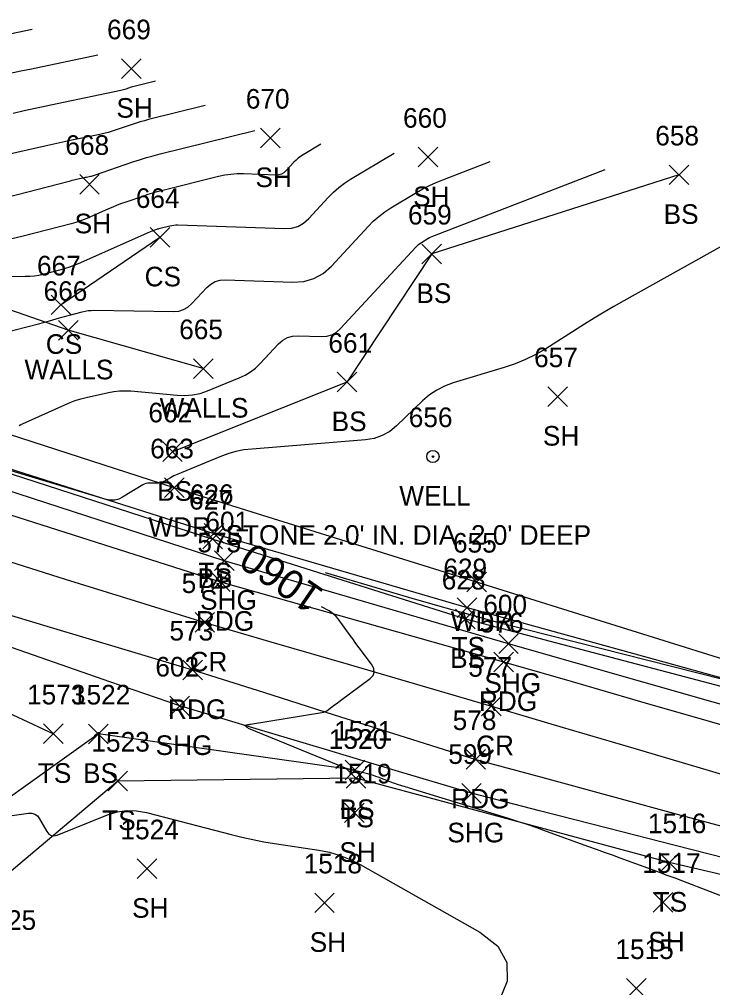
# Model space of a CAD drawing. Extents: x 1592612 to 1596497, y 111838 to 113741.
# Drawn here: x 1593003.9 to 1593074.6, y 113362.1 to 113460.8 of the extents above; entities that cross this region are included whole.
import ezdxf

# ---------------------------------------------------------------- set-up
doc = ezdxf.new("R2010")
doc.units = 0
for name, color, linetype in [('L_A', 7, 'Continuous'), ('L_I', 7, 'Continuous'), ('L_TIC', 7, 'Continuous'), ('LAWA', 7, 'Continuous'), ('LELB', 7, 'Continuous'), ('LSOGCMA', 7, 'Continuous'), ('LSOGCMA_T', 7, 'Continuous'), ('LSOGCMI', 7, 'Continuous'), ('LWS', 7, 'Continuous'), ('P_A', 7, 'Continuous'), ('P_I', 7, 'Continuous'), ('P_TIC', 7, 'Continuous'), ('PEU', 7, 'Continuous'), ('PRC', 7, 'Continuous'), ('PSU', 7, 'Continuous'), ('U_A', 7, 'Continuous'), ('U_C', 7, 'Continuous'), ('U_I', 7, 'Continuous'), ('UWW', 7, 'Continuous')]:
    doc.layers.add(name, color=color, linetype=linetype)

msp = doc.modelspace()

# ---------------------------------------------------------------- linework, layer by layer
at = {"layer": 'L_TIC'}
for points in [[(1593014.335, 113454.79), (1593016.335, 113456.79)], [(1593016.335, 113454.79), (1593014.335, 113456.79)], [(1593028.518, 113447.717), (1593030.518, 113449.717)], [(1593030.518, 113447.717), (1593028.518, 113449.717)], [(1593044.604, 113445.772), (1593046.604, 113447.772)], [(1593046.604, 113445.772), (1593044.604, 113447.772)], [(1593070.196, 113443.965), (1593072.196, 113445.965)], [(1593072.196, 113443.965), (1593070.196, 113445.965)], [(1593010.076, 113443.003), (1593012.076, 113445.003)], [(1593012.076, 113443.003), (1593010.076, 113445.003)], [(1593017.258, 113437.593), (1593019.258, 113439.593)], [(1593019.258, 113437.593), (1593017.258, 113439.593)], [(1593044.981, 113435.899), (1593046.981, 113437.899)], [(1593046.981, 113435.899), (1593044.981, 113437.899)], [(1593007.179, 113430.713), (1593009.179, 113432.713)], [(1593009.179, 113430.713), (1593007.179, 113432.713)], [(1593007.908, 113428.114), (1593009.908, 113430.114)], [(1593009.908, 113428.114), (1593007.908, 113430.114)], [(1593021.683, 113424.211), (1593023.683, 113426.211)], [(1593023.683, 113424.211), (1593021.683, 113426.211)], [(1593036.335, 113422.831), (1593038.335, 113424.831)], [(1593038.335, 113422.831), (1593036.335, 113424.831)], [(1593057.836, 113421.356), (1593059.836, 113423.356)], [(1593059.836, 113421.356), (1593057.836, 113423.356)], [(1593018.544, 113415.731), (1593020.544, 113417.731)], [(1593020.544, 113415.731), (1593018.544, 113417.731)], [(1593018.72, 113412.06), (1593020.72, 113414.06)], [(1593020.72, 113412.06), (1593018.72, 113414.06)], [(1593022.772, 113407.407), (1593024.772, 113409.407)], [(1593024.772, 113407.407), (1593022.772, 113409.407)], [(1593022.641, 113406.833), (1593024.641, 113408.833)], [(1593024.641, 113406.833), (1593022.641, 113408.833)], [(1593049.562, 113402.447), (1593051.562, 113404.447)], [(1593051.562, 113402.447), (1593049.562, 113404.447)], [(1593048.589, 113399.837), (1593050.589, 113401.837)], [(1593050.589, 113399.837), (1593048.589, 113401.837)], [(1593048.418, 113398.686), (1593050.418, 113400.686)], [(1593050.418, 113398.686), (1593048.418, 113400.686)], [(1593006.402, 113386.97), (1593008.402, 113388.97)], [(1593008.402, 113386.97), (1593006.402, 113388.97)], [(1593010.98, 113386.959), (1593012.98, 113388.959)], [(1593012.98, 113386.959), (1593010.98, 113388.959)], [(1593037.15, 113383.278), (1593039.15, 113385.278)], [(1593039.15, 113383.278), (1593037.15, 113385.278)], [(1593037.268, 113382.436), (1593039.268, 113384.436)], [(1593039.268, 113382.436), (1593037.268, 113384.436)], [(1593012.967, 113382.154), (1593014.967, 113384.154)], [(1593014.967, 113382.154), (1593012.967, 113384.154)], [(1593037.078, 113378.911), (1593039.078, 113380.911)], [(1593039.078, 113378.911), (1593037.078, 113380.911)], [(1593069.216, 113373.835), (1593071.216, 113375.835)], [(1593071.216, 113373.835), (1593069.216, 113375.835)], [(1593015.932, 113373.213), (1593017.932, 113375.213)], [(1593017.932, 113373.213), (1593015.932, 113375.213)], [(1593034.047, 113369.735), (1593036.047, 113371.735)], [(1593036.047, 113369.735), (1593034.047, 113371.735)], [(1593068.583, 113369.781), (1593070.583, 113371.781)], [(1593070.583, 113369.781), (1593068.583, 113371.781)], [(1593065.844, 113361.005), (1593067.844, 113363.005)], [(1593067.844, 113361.005), (1593065.844, 113363.005)]]:
    msp.add_lwpolyline(points, dxfattribs=at)
at = {"layer": 'LAWA'}
msp.add_lwpolyline([(1593169.611, 113375.165), (1593118.398, 113387.407), (1593080.143, 113394.184), (1593050.562, 113403.447), (1593019.72, 113413.06), (1592995.657, 113420.841), (1592970.681, 113431.184), (1592941.873, 113445.585), (1592917.884, 113456.286)], dxfattribs=at)
at = {"layer": 'LELB'}
for points in [[(1592908.46, 113460.258), (1592922.596, 113449.566), (1592933.267, 113441.549), (1592945.1, 113436.529), (1592970.28, 113425.515), (1592997.076, 113416.402), (1593023.641, 113407.833), (1593049.418, 113399.686), (1593079.204, 113391.835), (1593097.266, 113387.672), (1593130.658, 113380.878), (1593168.554, 113372.43)], [(1593071.196, 113444.965), (1593045.981, 113436.9), (1593037.335, 113423.831), (1593019.544, 113416.731)], [(1593018.258, 113438.593), (1593008.179, 113431.713)], [(1592945.373, 113437.303), (1592970.416, 113426.096), (1592997.179, 113416.812), (1593023.772, 113408.406), (1593049.589, 113400.837), (1593079.367, 113392.638), (1593097.503, 113388.59), (1593131.295, 113382.361), (1593169.279, 113374.833)], [(1593022.223, 113298.621), (1592996.05, 113319.251), (1592973.737, 113329.884), (1592951.567, 113338.734), (1592939.58, 113363.449), (1592930.763, 113371.375), (1592929.879, 113381.446), (1592924.735, 113386.602), (1592927.418, 113411.322), (1592932.961, 113414.131), (1592945.073, 113412.416), (1592963.598, 113404.825), (1592977.398, 113399.854), (1592996.446, 113393.062), (1593007.402, 113387.97)], [(1593038.151, 113384.278), (1593011.98, 113387.959), (1592995.33, 113376.06), (1592980.31, 113354.964), (1592972.203, 113338.996)], [(1593157.216, 113351.758), (1593128.266, 113360.771), (1593100.017, 113367.909), (1593070.216, 113374.835), (1593038.268, 113383.437), (1593013.967, 113383.154), (1593000.038, 113371.416), (1592985.819, 113350.727), (1592975.861, 113332.672)]]:
    msp.add_lwpolyline(points, dxfattribs=at)
at = {"layer": 'LSOGCMA'}
for points in [[(1593001.623, 113459.084), (1593005.243, 113459.837)], [(1593034.685, 113448.092), (1593032.859, 113446.998), (1593032.608, 113446.835), (1593032.37, 113446.656), (1593032.145, 113446.46), (1593031.935, 113446.247), (1593031.118, 113445.364), (1593030.902, 113445.172), (1593030.662, 113445.038), (1593030.397, 113444.961), (1593030.109, 113444.943), (1593026.801, 113445.058), (1593026.152, 113445.058), (1593025.508, 113445.013), (1593024.868, 113444.924), (1593024.233, 113444.789), (1593018.411, 113443.345), (1593017.952, 113443.225), (1593017.495, 113443.096), (1593017.041, 113442.956), (1593016.591, 113442.807), (1593014.793, 113442.189), (1593014.346, 113442.029), (1593013.902, 113441.861), (1593013.462, 113441.682), (1593013.026, 113441.495), (1593011.115, 113440.648), (1593010.649, 113440.453), (1593010.175, 113440.277), (1593009.695, 113440.121), (1593009.208, 113439.985), (1593004.159, 113438.682), (1593003.15, 113438.455)], [(1593035.109, 113404.404), (1593043.616, 113401.897), (1593046.557, 113401.047), (1593049.505, 113400.225), (1593052.462, 113399.432), (1593055.426, 113398.668), (1593078.233, 113392.909)], [(1593077.227, 113370.76), (1593071.605, 113372.928), (1593070.809, 113373.233), (1593070.011, 113373.534), (1593069.212, 113373.832), (1593068.412, 113374.126), (1593065.208, 113375.295), (1593064.407, 113375.587), (1593063.605, 113375.879), (1593062.804, 113376.17), (1593062.002, 113376.461), (1593057.695, 113378.022), (1593056.708, 113378.373), (1593055.716, 113378.712), (1593054.721, 113379.039), (1593053.722, 113379.353), (1593043.706, 113382.432), (1593043.542, 113382.483), (1593043.378, 113382.533), (1593043.215, 113382.584), (1593043.051, 113382.635), (1593042.397, 113382.839), (1593042.234, 113382.891), (1593042.072, 113382.946), (1593041.911, 113383.004), (1593041.751, 113383.065), (1593040.515, 113383.544), (1593040.285, 113383.63), (1593040.053, 113383.709), (1593039.819, 113383.782), (1593039.582, 113383.848), (1593038.249, 113384.203), (1593038.203, 113384.214), (1593038.157, 113384.223), (1593038.11, 113384.231), (1593038.063, 113384.236), (1593037.873, 113384.253), (1593037.827, 113384.258), (1593037.782, 113384.266), (1593037.737, 113384.277), (1593037.693, 113384.291), (1593037.517, 113384.35), (1593037.474, 113384.365), (1593037.43, 113384.381), (1593037.387, 113384.397), (1593037.344, 113384.415), (1593027.307, 113388.521), (1593027.258, 113388.543), (1593027.211, 113388.569), (1593027.167, 113388.598), (1593027.124, 113388.631), (1593026.958, 113388.768), (1593026.929, 113388.799), (1593026.923, 113388.825), (1593026.94, 113388.844), (1593026.981, 113388.857), (1593027.241, 113388.908), (1593027.301, 113388.92), (1593027.362, 113388.931), (1593027.423, 113388.941), (1593027.485, 113388.952), (1593034.763, 113390.138), (1593034.95, 113390.18), (1593035.127, 113390.244), (1593035.295, 113390.329), (1593035.454, 113390.437), (1593036.07, 113390.909), (1593036.224, 113391.027), (1593036.379, 113391.144), (1593036.534, 113391.261), (1593036.689, 113391.377), (1593039.692, 113393.606), (1593039.995, 113393.905), (1593040.129, 113394.23), (1593040.096, 113394.58), (1593039.895, 113394.955), (1593038.72, 113396.555), (1593038.453, 113396.918), (1593038.187, 113397.281), (1593037.921, 113397.644), (1593037.654, 113398.007), (1593036.428, 113399.679), (1593036.232, 113399.919), (1593036.013, 113400.135), (1593035.773, 113400.327), (1593035.511, 113400.493), (1593034.742, 113400.926)]]:
    msp.add_lwpolyline(points, dxfattribs=at)
at = {"layer": 'LSOGCMI'}
for points in [[(1593011.914, 113457.162), (1593005.15, 113455.755), (1593004.075, 113455.529), (1593003.001, 113455.299)], [(1593003.276, 113451.262), (1593004.402, 113451.514), (1593005.528, 113451.761), (1593006.656, 113452.003), (1593007.785, 113452.241), (1593014.284, 113453.593), (1593014.423, 113453.624), (1593014.56, 113453.659), (1593014.696, 113453.699), (1593014.831, 113453.743), (1593015.368, 113453.928), (1593015.502, 113453.972), (1593015.638, 113454.014), (1593015.774, 113454.053), (1593015.912, 113454.088), (1593017.806, 113454.558)], [(1593022.877, 113452.029), (1593017.095, 113450.594), (1593016.676, 113450.485), (1593016.259, 113450.367), (1593015.845, 113450.24), (1593015.434, 113450.103), (1593013.795, 113449.539), (1593013.383, 113449.405), (1593012.968, 113449.284), (1593012.549, 113449.176), (1593012.126, 113449.081), (1593009.284, 113448.489), (1593008.669, 113448.36), (1593008.055, 113448.228), (1593007.441, 113448.094), (1593006.828, 113447.957), (1593001.517, 113446.758)], [(1593001.456, 113442.383), (1593008.997, 113444.328), (1593009.154, 113444.368), (1593009.312, 113444.407), (1593009.471, 113444.445), (1593009.629, 113444.481), (1593010.38, 113444.651), (1593010.48, 113444.673), (1593010.581, 113444.695), (1593010.682, 113444.717), (1593010.782, 113444.738), (1593011.186, 113444.822), (1593011.286, 113444.845), (1593011.386, 113444.87), (1593011.484, 113444.899), (1593011.582, 113444.931), (1593015.5, 113446.279), (1593016.188, 113446.507), (1593016.88, 113446.72), (1593017.577, 113446.918), (1593018.279, 113447.1), (1593027.949, 113449.499)], [(1592997.854, 113434.611), (1593004.526, 113434.619), (1593004.992, 113434.635), (1593005.454, 113434.679), (1593005.913, 113434.752), (1593006.367, 113434.854), (1593008.179, 113435.322), (1593008.629, 113435.448), (1593009.072, 113435.592), (1593009.51, 113435.754), (1593009.94, 113435.934), (1593017.23, 113439.163), (1593017.316, 113439.2), (1593017.402, 113439.235), (1593017.49, 113439.268), (1593017.577, 113439.299), (1593017.93, 113439.421), (1593018.019, 113439.45), (1593018.108, 113439.477), (1593018.198, 113439.503), (1593018.288, 113439.526), (1593019.286, 113439.774), (1593019.483, 113439.816), (1593019.682, 113439.843), (1593019.882, 113439.857), (1593020.084, 113439.857), (1593030.964, 113439.48), (1593031.67, 113439.525), (1593032.317, 113439.712), (1593032.906, 113440.04), (1593033.435, 113440.51), (1593035.433, 113442.672), (1593035.95, 113443.192), (1593036.499, 113443.672), (1593037.081, 113444.111), (1593037.696, 113444.51), (1593042.166, 113447.188)], [(1593000.666, 113428.453), (1593005.996, 113429.821), (1593006.249, 113429.887), (1593006.502, 113429.954), (1593006.754, 113430.022), (1593007.006, 113430.091), (1593008.013, 113430.37), (1593008.265, 113430.44), (1593008.517, 113430.509), (1593008.769, 113430.578), (1593009.021, 113430.647), (1593010.326, 113430.999), (1593010.629, 113431.07), (1593010.934, 113431.119), (1593011.242, 113431.147), (1593011.553, 113431.153), (1593019.644, 113431.032), (1593020.181, 113431.076), (1593020.674, 113431.225), (1593021.122, 113431.478), (1593021.526, 113431.835), (1593023.051, 113433.475), (1593023.454, 113433.831), (1593023.902, 113434.08), (1593024.395, 113434.221), (1593024.932, 113434.255), (1593031.819, 113434.016), (1593032.943, 113434.088), (1593033.973, 113434.385), (1593034.909, 113434.908), (1593035.751, 113435.656), (1593039.496, 113439.707), (1593040.026, 113440.241), (1593040.59, 113440.734), (1593041.188, 113441.186), (1593041.82, 113441.595), (1593044.415, 113443.15), (1593045.071, 113443.524), (1593045.741, 113443.869), (1593046.426, 113444.184), (1593047.124, 113444.471), (1593051.942, 113446.325)], [(1593003.887, 113419.417), (1593004.068, 113419.506), (1593004.25, 113419.59), (1593008.557, 113421.527), (1593009.09, 113421.751), (1593009.632, 113421.948), (1593010.183, 113422.117), (1593010.743, 113422.26), (1593013.001, 113422.776), (1593013.567, 113422.882), (1593014.136, 113422.942), (1593014.708, 113422.957), (1593015.284, 113422.926), (1593020.017, 113422.484), (1593020.811, 113422.457), (1593021.591, 113422.523), (1593022.356, 113422.684), (1593023.108, 113422.939), (1593026.359, 113424.256), (1593026.948, 113424.532), (1593027.498, 113424.867), (1593028.007, 113425.261), (1593028.475, 113425.714), (1593030.36, 113427.74), (1593030.786, 113428.116), (1593031.259, 113428.379), (1593031.779, 113428.528), (1593032.345, 113428.564), (1593034.706, 113428.482), (1593035.273, 113428.519), (1593035.792, 113428.669), (1593036.264, 113428.932), (1593036.688, 113429.309), (1593044.355, 113437.603), (1593044.488, 113437.738), (1593044.63, 113437.861), (1593044.78, 113437.974), (1593044.938, 113438.077), (1593045.589, 113438.467), (1593045.753, 113438.561), (1593045.921, 113438.647), (1593046.093, 113438.726), (1593046.268, 113438.798), (1593063.672, 113445.496)], [(1593079.878, 113440.116), (1593065.591, 113432.12), (1593064.574, 113431.542), (1593063.564, 113430.951), (1593062.563, 113430.346), (1593061.569, 113429.728), (1593057.61, 113427.231), (1593056.604, 113426.643), (1593055.565, 113426.126), (1593054.494, 113425.682), (1593053.389, 113425.31), (1593048.159, 113423.741), (1593047.301, 113423.429), (1593046.498, 113423.023), (1593045.75, 113422.523), (1593045.057, 113421.93), (1593042.393, 113419.37), (1593041.695, 113418.8), (1593040.933, 113418.372), (1593040.108, 113418.086), (1593039.219, 113417.941), (1593027.656, 113417.011), (1593026.815, 113416.911), (1593025.989, 113416.746), (1593025.179, 113416.517), (1593024.384, 113416.223), (1593020.017, 113414.417), (1593019.841, 113414.34), (1593019.667, 113414.259), (1593019.496, 113414.172), (1593019.327, 113414.08), (1593018.651, 113413.697), (1593018.484, 113413.616), (1593018.312, 113413.56), (1593018.133, 113413.528), (1593017.948, 113413.519), (1593017.197, 113413.535), (1593017.012, 113413.526), (1593016.835, 113413.491), (1593016.665, 113413.431), (1593016.501, 113413.345), (1593014.458, 113412.085), (1593014.058, 113411.889), (1593013.646, 113411.787), (1593013.221, 113411.78), (1593012.784, 113411.866), (1593001.256, 113415.328)], [(1592999.858, 113379.167), (1593004.858, 113379.866), (1593005.206, 113379.87), (1593005.508, 113379.78), (1593005.764, 113379.595), (1593005.972, 113379.315), (1593006.711, 113378.006), (1593006.916, 113377.737), (1593007.163, 113377.585), (1593007.45, 113377.55), (1593007.779, 113377.631), (1593012.913, 113379.691), (1593013.89, 113379.999), (1593014.877, 113380.143), (1593015.875, 113380.124), (1593016.883, 113379.942), (1593025.516, 113377.692), (1593026.619, 113377.42), (1593027.728, 113377.178), (1593028.843, 113376.965), (1593029.964, 113376.781), (1593034.461, 113376.104), (1593035.568, 113375.886), (1593036.641, 113375.57), (1593037.681, 113375.157), (1593038.687, 113374.645), (1593050.883, 113367.731), (1593052.726, 113366.307), (1593053.657, 113364.641), (1593053.675, 113362.732), (1593052.782, 113360.581)]]:
    msp.add_lwpolyline(points, dxfattribs=at)
at = {"layer": 'LWS'}
msp.add_lwpolyline([(1593022.683, 113425.211), (1593008.908, 113429.114), (1592979.894, 113439.216)], dxfattribs=at)
at = {"layer": 'P_TIC'}
for points in [[(1593023.821, 113404.619), (1593025.821, 113406.619)], [(1593025.821, 113404.619), (1593023.821, 113406.619)], [(1593023.442, 113402.476), (1593025.442, 113404.476)], [(1593025.442, 113402.476), (1593023.442, 113404.476)], [(1593021.841, 113398.326), (1593023.841, 113400.326)], [(1593023.841, 113398.326), (1593021.841, 113400.326)], [(1593052.818, 113396.152), (1593054.818, 113398.152)], [(1593054.818, 113396.152), (1593052.818, 113398.152)], [(1593052.31, 113394.296), (1593054.31, 113396.296)], [(1593054.31, 113394.296), (1593052.31, 113396.296)], [(1593020.595, 113393.481), (1593022.595, 113395.481)], [(1593022.595, 113393.481), (1593020.595, 113395.481)], [(1593019.286, 113389.81), (1593021.286, 113391.81)], [(1593021.286, 113389.81), (1593019.286, 113391.81)], [(1593051.076, 113389.789), (1593053.076, 113391.789)], [(1593053.076, 113389.789), (1593051.076, 113391.789)], [(1593049.483, 113384.355), (1593051.483, 113386.355)], [(1593051.483, 113384.355), (1593049.483, 113386.355)], [(1593049.043, 113380.901), (1593051.043, 113382.901)], [(1593051.043, 113380.901), (1593049.043, 113382.901)]]:
    msp.add_lwpolyline(points, dxfattribs=at)
at = {"layer": 'PEU'}
for points in [[(1593003.018, 113410.299), (1593010.16, 113408.025), (1593017.301, 113405.751), (1593024.442, 113403.476), (1593031.659, 113401.431), (1593038.876, 113399.386), (1593046.093, 113397.341), (1593053.31, 113395.296), (1593060.299, 113393.287), (1593067.289, 113391.279), (1593074.278, 113389.27), (1593081.267, 113387.261), (1593088.257, 113385.323), (1593095.247, 113383.384), (1593102.237, 113381.446), (1593109.227, 113379.507), (1593116.551, 113377.543), (1593123.875, 113375.58)], [(1592999.818, 113401.035), (1593007.077, 113398.85), (1593014.336, 113396.666), (1593021.595, 113394.481), (1593028.817, 113392.2), (1593036.039, 113389.918), (1593043.261, 113387.637), (1593050.483, 113385.355), (1593057.456, 113383.464), (1593064.43, 113381.574), (1593071.403, 113379.683), (1593078.377, 113377.792), (1593085.465, 113375.859), (1593092.554, 113373.925), (1593099.643, 113371.992), (1593106.731, 113370.058), (1593113.913, 113368.024), (1593121.096, 113365.989)]]:
    msp.add_lwpolyline(points, dxfattribs=at)
at = {"layer": 'PRC'}
msp.add_lwpolyline([(1593001.474, 113405.968), (1593008.597, 113403.754), (1593015.719, 113401.54), (1593022.841, 113399.326), (1593030.15, 113397.192), (1593037.459, 113395.057), (1593044.767, 113392.923), (1593052.076, 113390.789), (1593059.056, 113388.725), (1593066.037, 113386.661), (1593073.017, 113384.597), (1593079.997, 113382.533), (1593086.953, 113380.624), (1593093.909, 113378.714), (1593100.865, 113376.805), (1593107.821, 113374.896), (1593115.173, 113372.97), (1593122.526, 113371.044)], dxfattribs=at)
at = {"layer": 'PSU'}
for points in [[(1593167.681, 113369.582), (1593139.7, 113376.255), (1593109.821, 113382.695), (1593081.736, 113389.175), (1593053.818, 113397.152), (1593024.821, 113405.619), (1592996.75, 113414.705), (1592967.822, 113425.179), (1592940.197, 113435.636), (1592911.843, 113443.034)], [(1593127.958, 113361.911), (1593120.671, 113363.837), (1593113.383, 113365.762), (1593106.096, 113367.687), (1593099.009, 113369.469), (1593091.923, 113371.25), (1593084.837, 113373.032), (1593077.751, 113374.814), (1593070.824, 113376.586), (1593063.897, 113378.357), (1593056.97, 113380.129), (1593050.043, 113381.901), (1593042.604, 113384.128), (1593035.164, 113386.355), (1593027.725, 113388.583), (1593020.286, 113390.81), (1593013.158, 113393.283), (1593006.031, 113395.756), (1592998.904, 113398.23)]]:
    msp.add_lwpolyline(points, dxfattribs=at)
at = {"layer": 'UWW'}
for radius in [0.625, 0.0833]:
    msp.add_circle((1593046.108, 113416.244), radius, dxfattribs=at)

# ---------------------------------------------------------------- texts
at = {"layer": 'L_A'}
for s, p in [('SH', (1593013.823, 113450.79)), ('SH', (1593028.006, 113443.717)), ('SH', (1593044.092, 113441.772)), ('BS', (1593069.637, 113439.965)), ('SH', (1593009.564, 113439.003)), ('CS', (1593016.699, 113433.593)), ('BS', (1593044.422, 113431.899)), ('CS', (1593006.62, 113426.713)), ('WALLS', (1593004.451, 113424.114)), ('WALLS', (1593018.226, 113420.211)), ('BS', (1593035.776, 113418.831)), ('SH', (1593057.324, 113417.356)), ('BS', (1593017.984, 113411.731)), ('WDR', (1593017.082, 113408.06)), ('TS', (1593022.182, 113403.407)), ('BS', (1593022.082, 113402.833)), ('WDR', (1593047.924, 113398.447)), ('TS', (1593047.998, 113395.837)), ('BS', (1593047.859, 113394.686)), ('TS', (1593005.812, 113382.97)), ('BS', (1593010.421, 113382.959)), ('BS', (1593036.591, 113379.278)), ('TS', (1593012.376, 113378.154)), ('TS', (1593036.678, 113378.436)), ('SH', (1593036.566, 113374.911)), ('TS', (1593068.626, 113369.835)), ('SH', (1593015.42, 113369.213)), ('SH', (1593033.536, 113365.735)), ('SH', (1593068.071, 113365.781))]:
    msp.add_text(s, height=2, dxfattribs=at).set_placement(p)
at = {"layer": 'L_I'}
for s, p in [('669', (1593012.871, 113458.79)), ('670', (1593027.022, 113451.717)), ('660', (1593043.061, 113449.772)), ('658', (1593068.786, 113447.965)), ('668', (1593008.62, 113447.003)), ('664', (1593015.801, 113441.593)), ('659', (1593043.564, 113439.899)), ('667', (1593005.723, 113434.713)), ('666', (1593006.396, 113432.114)), ('665', (1593020.226, 113428.211)), ('661', (1593035.445, 113426.831)), ('657', (1593056.426, 113425.356)), ('662', (1593017.087, 113419.731)), ('663', (1593017.263, 113416.06)), ('626', (1593021.308, 113411.407)), ('627', (1593021.232, 113410.833)), ('655', (1593048.152, 113406.447)), ('629', (1593047.172, 113403.837)), ('628', (1593047.008, 113402.686)), ('1573', (1593004.709, 113390.97)), ('1522', (1593009.287, 113390.959)), ('1520', (1593035.489, 113386.436)), ('1521', (1593036.025, 113387.278)), ('1523', (1593011.274, 113386.154)), ('1519', (1593035.944, 113382.911)), ('1516', (1593068.035, 113377.835)), ('1524', (1593014.239, 113377.213)), ('1518', (1593032.921, 113373.735)), ('1517', (1593067.457, 113373.781)), ('1525', (1592999.69, 113367.975)), ('1515', (1593064.718, 113365.005))]:
    msp.add_text(s, height=2, dxfattribs=at).set_placement(p)
at = {"layer": 'LSOGCMA_T'}
msp.add_text('1060', height=3, rotation=145.39475, dxfattribs=at).set_placement((1593035.167, 113402.541))
at = {"layer": 'P_A'}
for s, p in [('SHG', (1593022.356, 113400.619)), ('RDG', (1593021.93, 113398.476)), ('CR', (1593021.274, 113394.326)), ('SHG', (1593051.353, 113392.152)), ('RDG', (1593050.799, 113390.296)), ('RDG', (1593019.083, 113389.481)), ('SHG', (1593017.821, 113385.81)), ('CR', (1593050.509, 113385.789)), ('RDG', (1593047.971, 113380.355)), ('SHG', (1593047.579, 113376.901))]:
    msp.add_text(s, height=2, dxfattribs=at).set_placement(p)
at = {"layer": 'P_I'}
for s, p in [('601', (1593022.9, 113408.619)), ('575', (1593022.08, 113406.476)), ('574', (1593020.479, 113402.326)), ('600', (1593051.243, 113400.152)), ('576', (1593050.893, 113398.296)), ('573', (1593019.232, 113397.481)), ('602', (1593017.798, 113393.81)), ('577', (1593049.714, 113393.789)), ('578', (1593048.121, 113388.355)), ('599', (1593047.673, 113384.901))]:
    msp.add_text(s, height=2, dxfattribs=at).set_placement(p)
at = {"layer": 'U_A'}
msp.add_text('WELL', height=2, dxfattribs=at).set_placement((1593042.675, 113411.244))
at = {"layer": 'U_C'}
msp.add_text("STONE 2.0' IN. DIA. 2.0' DEEP", height=2, dxfattribs=at).set_placement((1593024.95, 113407.244))
at = {"layer": 'U_I'}
msp.add_text('656', height=2, dxfattribs=at).set_placement((1593043.643, 113419.244))

doc.saveas('drawing.dxf')
